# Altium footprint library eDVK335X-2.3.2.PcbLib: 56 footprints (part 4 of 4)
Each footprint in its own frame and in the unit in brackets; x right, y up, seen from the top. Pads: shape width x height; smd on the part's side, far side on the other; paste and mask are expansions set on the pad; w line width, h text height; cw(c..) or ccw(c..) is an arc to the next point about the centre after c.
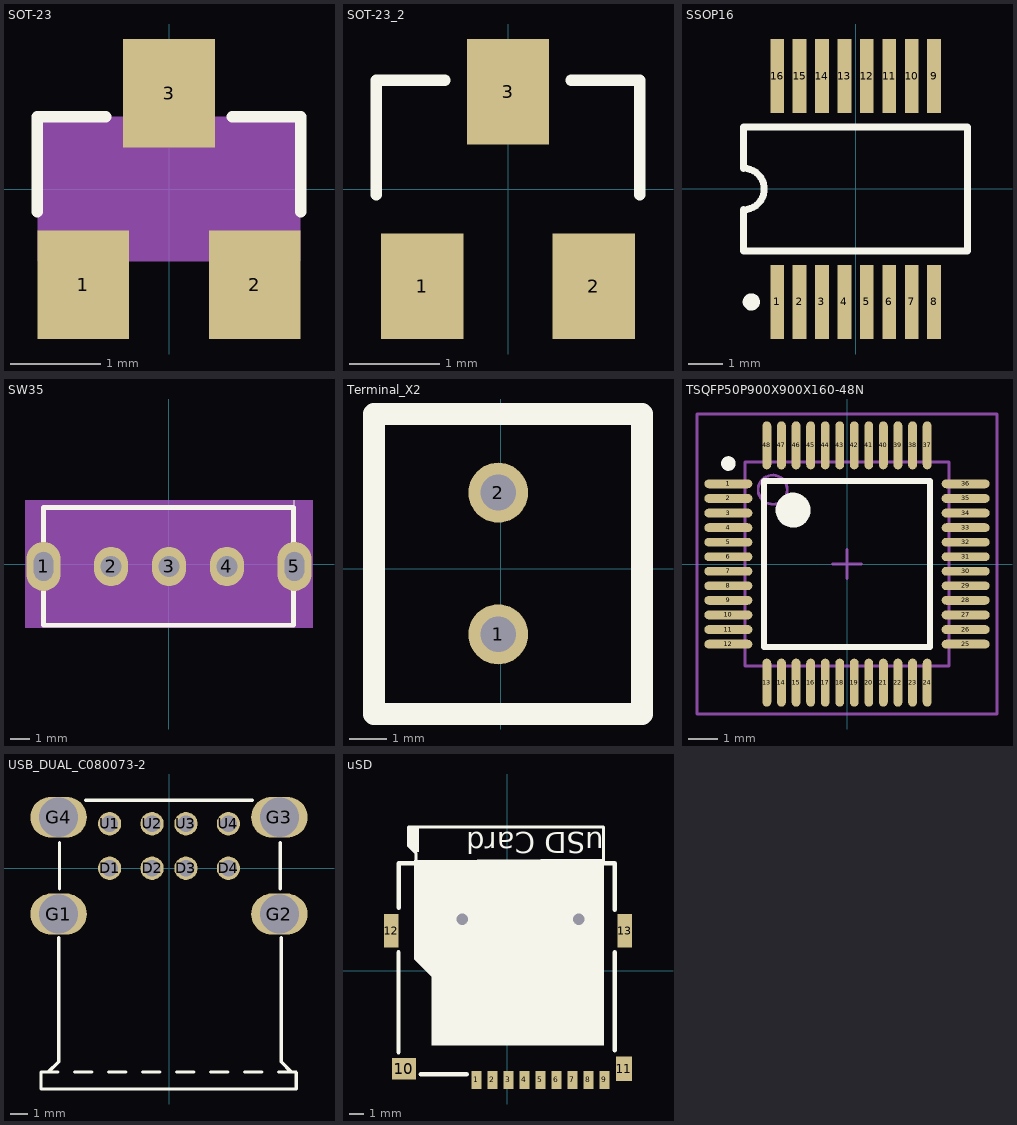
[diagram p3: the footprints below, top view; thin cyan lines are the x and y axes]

## SOT-23 [mm]
height 4.6
pads (3):
  rect 1.016x1.2 smd: 1(-0.95,-1.06) 2(0.95,-1.06) 3(0,1.06)
Top Overlay:
  lines w0.127: -1.46,-0.254 -1.46,0.8 -0.699,0.8 ; 0.699,0.8 1.46,0.8 1.46,-0.254
Mechanical 13:
  region: 0.229,0.839 -0.229,0.839 -0.229,1.422 0.229,1.422
  region: 1.168,-1.424 0.712,-1.424 0.712,-0.838 1.168,-0.838
  region: -0.711,-1.423 -1.169,-1.423 -1.169,-0.838 -0.711,-0.838
Mechanical 15:
  region: 1.45,-0.801 -1.451,-0.801 -1.451,0.8 1.45,0.8

## SOT-23_2 [mil]
pads (3):
  rect 36x46 smd: 1(-37.5,-42.5) 2(37.5,-42.5) 3(0,42.5)
Top Overlay:
  lines w5: -57.5,-2.5 -57.5,47.5 -27.5,47.5 ; 27.5,47.5 57.5,47.5 57.5,-2.5

## SSOP16 [mm] "SSOP; 16 Leads; Body Width 5.3 mm; Pitch 0.65 mm"
height 1.99
pads (16):
  rect 0.4x2.15 smd: 1(-2.275,-3.275) 2(-1.625,-3.275) 3(-0.975,-3.275) 4(-0.325,-3.275) 5(0.325,-3.275) 6(0.975,-3.275) 7(1.625,-3.275) 8(2.275,-3.275) 9(2.275,3.275) 10(1.625,3.275) 11(0.975,3.275) 12(0.325,3.275) 13(-0.325,3.275) 14(-0.975,3.275) 15(-1.625,3.275) 16(-2.275,3.275)
Top Overlay:
  circle w0.25: c-3.025,-3.275 r0.125
  lines w0.2: -3.25,-1.8 3.25,-1.8 3.25,1.8 -3.25,1.8 -3.25,0.6 cw(c-3.25,0) -3.25,-0.6 -3.25,-1.8

## SW35 [mil] "SW35"
pads (5):
  oval 70x100 / inner round 60 / far side oval 70x100 hole 39.37 slot 59.06 at 90 deg: 1(-255.91,-5) 5(255.91,-5)
  oval 70x80 / inner round 60 / far side oval 70x80 hole 43.31: 2(-118.11,-5) 3(0,-5) 4(118.11,-5)
Top Overlay:
  lines w1: 255,100 255,130 ; 255,100 255,130 ; 255,100 255,130
  lines w10: -255.91,-125 254.09,-125 254.09,115 -255.91,115 -255.91,-125
Mechanical 7:
  region: -292.9,-130 292.91,-130 292.91,130 -292.9,130
Mechanical 14:
  text "3" at 0,-15 h25
  text "2" at -118.11,-15 h25
  text "4" at 118.11,-15 h25
  text "1" at -255.91,-15 h25
  text "5" at 255.91,-15 h25
3D body: height 150, standoff 0, extent -292.9,-130 292.91,130

## Terminal_X2 [mm]
pads (2):
  round 1.624 hole 0.97: 1(-0.063,-1.778) 2(-0.063,2.062)
Top Overlay:
  lines w0.6: -3.429,-3.937 -3.429,4.193 3.831,4.193 3.831,-3.937 -3.429,-3.937

## TSQFP50P900X900X160-48N [mm] "TSQFP, 48-Leads, Body 9.0x9.0mm (max), Pitch 0.50mm, IPC Medium Density"
height 1.6
pads (48):
  oval 1.65x0.3 smd: 1(-4.075,2.75) 2(-4.075,2.25) 3(-4.075,1.75) 4(-4.075,1.25) 5(-4.075,0.75) 6(-4.075,0.25) 7(-4.075,-0.25) 8(-4.075,-0.75) 9(-4.075,-1.25) 10(-4.075,-1.75) 11(-4.075,-2.25) 12(-4.075,-2.75) 25(4.075,-2.75) 26(4.075,-2.25) 27(4.075,-1.75) 28(4.075,-1.25) 29(4.075,-0.75) 30(4.075,-0.25) 31(4.075,0.25) 32(4.075,0.75) 33(4.075,1.25) 34(4.075,1.75) 35(4.075,2.25) 36(4.075,2.75)
  oval 0.3x1.65 smd: 13(-2.75,-4.075) 14(-2.25,-4.075) 15(-1.75,-4.075) 16(-1.25,-4.075) 17(-0.75,-4.075) 18(-0.25,-4.075) 19(0.25,-4.075) 20(0.75,-4.075) 21(1.25,-4.075) 22(1.75,-4.075) 23(2.25,-4.075) 24(2.75,-4.075) 37(2.75,4.075) 38(2.25,4.075) 39(1.75,4.075) 40(1.25,4.075) 41(0.75,4.075) 42(0.25,4.075) 43(-0.25,4.075) 44(-0.75,4.075) 45(-1.25,4.075) 46(-1.75,4.075) 47(-2.25,4.075) 48(-2.75,4.075)
Top Overlay:
  circle w0.25: c-4.075,3.45 r0.125
  circle w0.6: c-1.85,1.85 r0.3
  lines w0.2: -2.85,-2.85 -2.85,2.85 2.85,2.85 2.85,-2.85 -2.85,-2.85
Mechanical 13:
  circle w0.1: c-2.55,2.55 r0.5
  lines w0.1: -3.5,-3.5 -3.5,3.5 3.5,3.5 3.5,-3.5 -3.5,-3.5
Mechanical 15:
  lines w0.1: -0.5,0 0.5,0 ; 0,-0.5 0,0.5 ; -5.15,-5.15 -5.15,5.15 5.15,5.15 5.15,-5.15 -5.15,-5.15
3D body: height 1.6, standoff 0.05, extent -3.5,-3.5 3.5,3.5

## USB_DUAL_C080073-2 [mil] "USB_DUAL_C080073-2"
pads (12):
  round 54 / inner round 60 / far side round 54 hole 39: D1(-137.79,0) D2(-39.37,0) D3(39.37,0) D4(137.79,0) U1(-137.79,103.15) U2(-39.37,103.15) U3(39.37,103.15) U4(137.79,103.15)
  oval 131x95 / inner round 60 / far side oval 131x95 hole 91: G1(-255.91,-106.3) G2(255.91,-106.3) G3(255.91,118.11) G4(-255.91,118.11)
Top Overlay:
  lines w7.87: -279.53,-472.44 -255.91,-448.82 -255.91,-161.42 ; -257.44,-472.44 -296.81,-472.44 -296.81,-510.28 -295.27,-511.81 295.28,-511.81 295.28,-473.98 293.74,-472.44 254.37,-472.44 ; -253.94,-47.24 -253.94,59.05 ; -218.07,-472.44 -178.7,-472.44 ; -192.91,157.48 192.91,157.48 ; -139.33,-472.44 -99.96,-472.44 ; -60.59,-472.44 -21.22,-472.44 ; 18.15,-472.44 57.52,-472.44 ; 96.89,-472.44 136.26,-472.44 ; 175.63,-472.44 215,-472.44 ; 257.87,-47.24 257.87,59.05 ; 259.84,-161.42 259.84,-448.82 283.46,-472.44
Mechanical 8:
  text "G3" at 252.9,115.35 h10
  text "U4" at 125.73,102.36 h10
  text "D4" at 125.73,-7.87 h10
  text "U3" at 27.31,94.49 h10
  text "U2" at -47.5,98.42 h10
  text "D3" at 23.37,0 h10
  text "D2" at -51.43,-3.94 h10
  text "G2" at 252.9,-109.84 h10
  text "U1" at -149.86,98.42 h10
  text "G4" at -265.21,115.35 h10
  text "D1" at -153.79,-3.94 h10
  text "G1" at -261.27,-109.84 h10
Mechanical 10:
  text "USB-HOSTX2" at -106.3,-212.6 h31

## uSD [mm]
height 4.8
pads (15):
  rect 0.7x1.25 smd: 1(-2.134,-7.493) 2(-1.034,-7.493) 3(0.066,-7.493) 4(1.166,-7.493) 5(2.266,-7.493) 6(3.366,-7.493) 7(4.466,-7.493) 8(5.566,-7.493) 9(6.666,-7.493)
  rect 1.65x1.5 smd: 10(-7.112,-6.731)
  rect 1.1x1.7 smd: 11(8.001,-6.731)
  rect 1x2.3 smd: 12(-8.001,2.767) 13(8.074,2.767)
  round 0 hole 0.8 unplated: ""(-3.1,3.538) ""(4.9,3.538)
Top Overlay:
  region: -6.8,9.9 -6.8,8.6 -6.4,8.2 -6.1,8.2 -6.1,9.9
  region: -6.4,7.6 -6.4,0.8 -5.2,-0.4 -5.2,-5.1 6.6,-5.1 6.6,7.7
  lines w0.2: -6.3,7.393 -6.3,8.1 -6.8,8.6 -6.8,9.9 6.6,9.9 6.6,7.398
  lines w0.3: -7.493,-5.588 -7.493,1.27 ; -7.479,7.38 -7.466,7.393 ; -7.466,4.345 -7.466,7.393 ; -5.969,-7.112 -2.794,-7.112 ; 7.366,-5.461 7.366,1.27 ; 7.366,4.191 7.366,7.393 -7.466,7.393
  text "uSD Card" at 6.6,10 h2.5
